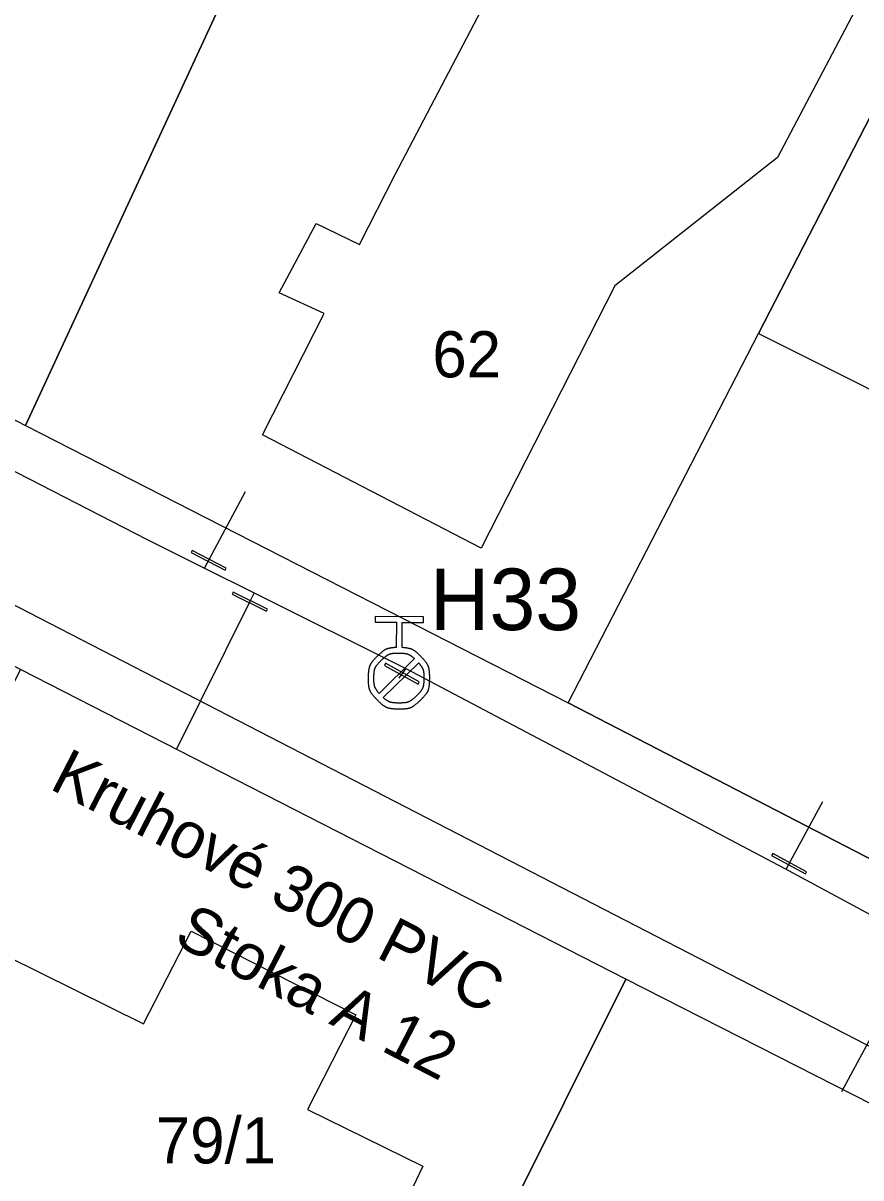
# Model space of a CAD drawing. Extents: x -559654 to -559448, y -1076607 to -1076478.
# Drawn here: x -559538.26 to -559511.05, y -1076565.25 to -1076527.73 of the extents above; entities that cross this region are included whole.
import ezdxf

# ---------------------------------------------------------------- set-up
doc = ezdxf.new("R2010")
doc.units = 0
for name, color, linetype in [('Armatura vodovodní', 7, 'Continuous'), ('Default', 7, 'Continuous'), ('Hydrant', 7, 'Continuous'), ('Kanalizační stoka', 7, 'Continuous'), ('Označení hydrantu', 7, 'Continuous'), ('Označení stoky', 7, 'Continuous'), ('Parcela-polygon', 7, 'Continuous'), ('Parcela-text', 7, 'Continuous'), ('Popis kmenové stoky', 7, 'Continuous'), ('Vodovodní přípojka', 7, 'Continuous'), ('Vodovodní řad', 7, 'Continuous')]:
    doc.layers.add(name, color=color, linetype=linetype)

msp = doc.modelspace()

# ---------------------------------------------------------------- linework, layer by layer
at = {"layer": 'Armatura vodovodní'}
for points in [[(-559531.698, -1076545.507), (-559531.662, -1076545.438), (-559532.771, -1076544.861), (-559532.807, -1076544.93)], [(-559530.355, -1076546.84), (-559530.32, -1076546.77), (-559531.44, -1076546.214), (-559531.475, -1076546.284)], [(-559525.436, -1076549.206), (-559525.398, -1076549.138), (-559526.49, -1076548.529), (-559526.528, -1076548.597)], [(-559512.852, -1076555.369), (-559512.815, -1076555.301), (-559513.914, -1076554.706), (-559513.952, -1076554.774)]]:
    msp.add_lwpolyline(points, close=True, dxfattribs=at)
at = {"layer": 'Default'}
for points in [[(-559526.141, -1076548.015), (-559526.38, -1076548.032), (-559526.586, -1076548.127), (-559526.759, -1076548.3)], [(-559525.341, -1076548.31), (-559525.511, -1076548.136), (-559525.716, -1076548.038), (-559525.954, -1076548.017)], [(-559526.759, -1076548.3), (-559526.954, -1076548.494), (-559527.053, -1076548.729), (-559527.055, -1076549.007)], [(-559526.869, -1076549.004), (-559526.868, -1076548.779), (-559526.787, -1076548.588), (-559526.628, -1076548.431)], [(-559526.628, -1076548.431), (-559526.469, -1076548.274), (-559526.276, -1076548.196), (-559526.051, -1076548.197)], [(-559526.051, -1076548.197), (-559525.857, -1076548.199), (-559525.688, -1076548.259), (-559525.545, -1076548.377)], [(-559525.413, -1076548.511), (-559525.299, -1076548.655), (-559525.243, -1076548.823), (-559525.244, -1076549.016)], [(-559525.055, -1076549.021), (-559525.053, -1076548.744), (-559525.148, -1076548.507), (-559525.341, -1076548.31)], [(-559527.055, -1076549.007), (-559527.057, -1076549.283), (-559526.961, -1076549.519), (-559526.767, -1076549.715)], [(-559526.697, -1076549.513), (-559526.813, -1076549.368), (-559526.871, -1076549.198), (-559526.869, -1076549.004)], [(-559525.244, -1076549.016), (-559525.246, -1076549.241), (-559525.327, -1076549.432), (-559525.487, -1076549.589)], [(-559525.353, -1076549.725), (-559525.156, -1076549.532), (-559525.057, -1076549.297), (-559525.055, -1076549.021)], [(-559526.063, -1076549.822), (-559526.256, -1076549.821), (-559526.423, -1076549.763), (-559526.565, -1076549.647)], [(-559525.487, -1076549.589), (-559525.647, -1076549.746), (-559525.839, -1076549.824), (-559526.063, -1076549.822)], [(-559526.767, -1076549.715), (-559526.573, -1076549.911), (-559526.339, -1076550.01), (-559526.064, -1076550.012)], [(-559526.064, -1076550.012), (-559525.787, -1076550.014), (-559525.55, -1076549.918), (-559525.353, -1076549.725)]]:
    msp.add_open_spline(points, degree=2, dxfattribs=at)
at = {"layer": 'Hydrant'}
for points in [[(-559525.954, -1076548.017), (-559525.948, -1076547.2), (-559525.261, -1076547.205), (-559525.259, -1076547.018), (-559526.822, -1076547.006), (-559526.823, -1076547.194), (-559526.136, -1076547.199), (-559526.141, -1076548.015)], [(-559525.545, -1076548.377), (-559526.697, -1076549.513)], [(-559526.565, -1076549.647), (-559525.413, -1076548.511)]]:
    msp.add_lwpolyline(points, dxfattribs=at)
at = {"layer": 'Kanalizační stoka'}
msp.add_lwpolyline([(-559500.698, -1076566.177), (-559542.148, -1076544.787)], dxfattribs=at)
at = {"layer": 'Parcela-polygon'}
for points in [[(-559598.18, -1076518.16), (-559629.27, -1076502.23), (-559633.72, -1076500.39), (-559623.33, -1076497.36), (-559616.19, -1076501.28), (-559573.81, -1076522.62), (-559555.89, -1076531.62), (-559538.18, -1076540.8), (-559520.56, -1076549.81), (-559502.55, -1076559.13), (-559485.32, -1076568.19), (-559489.07, -1076574.14), (-559505.11, -1076565.7), (-559518.69, -1076558.79), (-559538.34, -1076548.73), (-559546.54, -1076544.48), (-559559.21, -1076537.91), (-559568.79, -1076532.99), (-559577, -1076528.76), (-559595.22, -1076519.64)], [(-559530.49, -1076541.11), (-559528.48, -1076537.16), (-559529.94, -1076536.49), (-559528.74, -1076534.24), (-559527.34, -1076534.92), (-559526.18, -1076532.65), (-559523.27, -1076527.09), (-559521.78, -1076524.27), (-559517.31, -1076526.7), (-559516.36, -1076524.39), (-559511.15, -1076527.15), (-559513.76, -1076532.1), (-559519.04, -1076536.27), (-559523.38, -1076544.79)], [(-559511.22, -1076539.4), (-559500.9, -1076544.64), (-559496.26, -1076546.97), (-559502.55, -1076559.13), (-559520.56, -1076549.81), (-559514.38, -1076537.81)], [(-559545.74, -1076569.06), (-559539.94, -1076557.48), (-559534.35, -1076560.25), (-559532.8, -1076557.23), (-559527.46, -1076559.95), (-559529.02, -1076563.03), (-559525.28, -1076564.87), (-559528.02, -1076570.62), (-559530.78, -1076569.31), (-559530.97, -1076569.71), (-559536.96, -1076566.67), (-559539.65, -1076572.09)]]:
    msp.add_lwpolyline(points, close=True, dxfattribs=at)
for points in [[(-559545.04, -1076510.049), (-559555.89, -1076531.62), (-559538.18, -1076540.8), (-559527.504, -1076517.73)], [(-559527.504, -1076517.73), (-559538.18, -1076540.8), (-559520.56, -1076549.81), (-559514.38, -1076537.81), (-559508.359, -1076526.116)], [(-559513.76, -1076532.1), (-559519.04, -1076536.27), (-559523.38, -1076544.79), (-559530.49, -1076541.11), (-559528.48, -1076537.16), (-559529.94, -1076536.49), (-559528.74, -1076534.24), (-559527.34, -1076534.92), (-559526.18, -1076532.65), (-559523.27, -1076527.09), (-559521.78, -1076524.27), (-559517.31, -1076526.7), (-559516.36, -1076524.39), (-559511.15, -1076527.15), (-559513.76, -1076532.1)], [(-559508.359, -1076526.116), (-559514.38, -1076537.81), (-559511.22, -1076539.4), (-559500.9, -1076544.64), (-559496.26, -1076546.97), (-559489.702, -1076534.288)], [(-559529.198, -1076579.881), (-559524.71, -1076570.87), (-559518.69, -1076558.79), (-559538.34, -1076548.73), (-559542.4, -1076556.72), (-559545.15, -1076562.4), (-559547.78, -1076561.13), (-559550.05, -1076564.71), (-559551.22, -1076566.57), (-559551.999, -1076568.129)], [(-559539.65, -1076572.09), (-559545.74, -1076569.06), (-559539.94, -1076557.48), (-559534.35, -1076560.25), (-559532.8, -1076557.23), (-559527.46, -1076559.95), (-559529.02, -1076563.03), (-559525.28, -1076564.87), (-559528.02, -1076570.62), (-559530.82, -1076576.47), (-559539.65, -1076572.09)], [(-559515.683, -1076586.846), (-559505.11, -1076565.7), (-559518.69, -1076558.79), (-559524.71, -1076570.87), (-559522.23, -1076572.11), (-559514.5, -1076576.01), (-559517.09, -1076580.05), (-559519.553, -1076584.851)]]:
    msp.add_lwpolyline(points, dxfattribs=at)
at = {"layer": 'Vodovodní přípojka'}
for points in [[(-559532.371, -1076545.439), (-559531.038, -1076542.95)], [(-559530.757, -1076546.244), (-559530.897, -1076546.527), (-559533.276, -1076551.322)], [(-559513.482, -1076555.219), (-559512.29, -1076553.017)], [(-559509.049, -1076557.576), (-559511.687, -1076562.451)]]:
    msp.add_lwpolyline(points, dxfattribs=at)
at = {"layer": 'Vodovodní řad'}
for points in [[(-559593.267, -1076491.395), (-559624.029, -1076495.839), (-559624.9, -1076495.951), (-559625.488, -1076496.027), (-559625.404, -1076497.654), (-559619.475, -1076500.701), (-559618.245, -1076501.333), (-559615.438, -1076502.776), (-559591.192, -1076515.237), (-559582.087, -1076519.916), (-559544.618, -1076539.173), (-559534.23, -1076544.512), (-559532.371, -1076545.439), (-559530.757, -1076546.244), (-559525.83, -1076548.702), (-559513.543, -1076555.186), (-559509.507, -1076557.365), (-559508.97, -1076557.619), (-559494.604, -1076565.581), (-559494.539, -1076565.616), (-559485.627, -1076570.145)], [(-559525.963, -1076548.868), (-559526.055, -1076549.012)], [(-559525.83, -1076548.702), (-559525.963, -1076548.868)]]:
    msp.add_lwpolyline(points, dxfattribs=at)

# ---------------------------------------------------------------- texts
at = {"layer": 'Označení hydrantu'}
msp.add_text('H33', height=2, dxfattribs=at).set_placement((-559525.046, -1076547.452))
at = {"layer": 'Označení stoky'}
msp.add_text('Stoka A 12', height=1.5, rotation=332.7043, dxfattribs=at).set_placement((-559533.416, -1076557.617))
at = {"layer": 'Parcela-text'}
for s, p in [('62', (-559524.97, -1076539.24)), ('79/1', (-559533.95, -1076564.78))]:
    msp.add_text(s, height=1.5, dxfattribs=at).set_placement(p)
at = {"layer": 'Popis kmenové stoky'}
msp.add_text('Kruhové 300 PVC', height=1.5, rotation=332.7043, dxfattribs=at).set_placement((-559537.444, -1076552.586))

doc.saveas('drawing.dxf')
